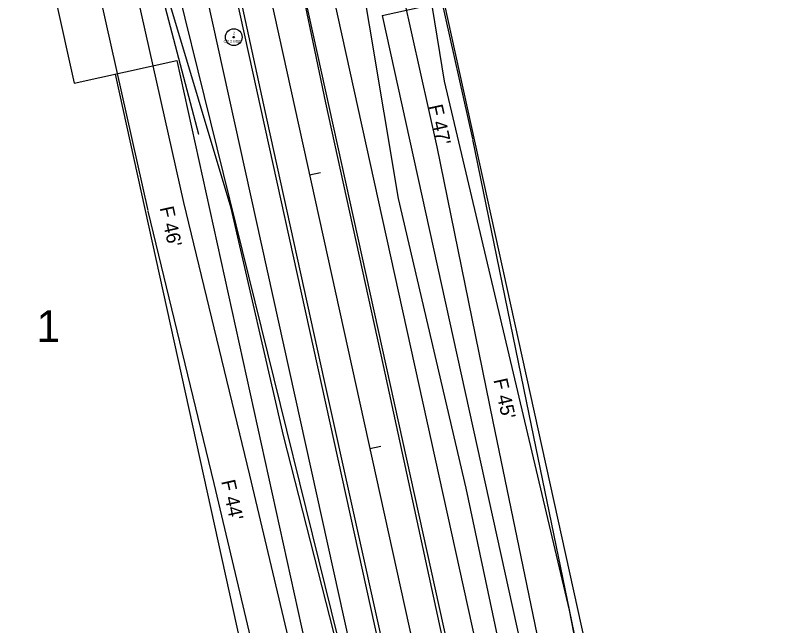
# Model space of a CAD drawing. Extents: x 2519952 to 2531965, y 848341 to 887632.
# Drawn here: x 2524424.7 to 2524699.1, y 869571 to 869788.7 of the extents above; entities that cross this region are included whole.
import ezdxf

# ---------------------------------------------------------------- set-up
doc = ezdxf.new("R2010")
doc.units = 0
for name, color, linetype in [('RD_EV_JW', 7, 'Continuous'), ('RD_EX_DV_Prop', 7, 'Continuous'), ('RD_EX_DV_TX_Prop', 7, 'Continuous'), ('RD_EX_H2O', 7, 'Continuous'), ('RD_EX_Road', 7, 'Continuous'), ('RD_EX_RW', 7, 'Continuous'), ('RD_EX_VEG', 7, 'Continuous'), ('RD_HC_Cl', 7, 'Continuous'), ('RD_HC_Data', 7, 'Continuous'), ('RD_HC_Data_Tic', 7, 'Continuous'), ('RD_HC_txCode', 7, 'Continuous'), ('RD_PD_CstnLmt', 7, 'Continuous'), ('RD_PD_DR_ErosCtrl', 7, 'Continuous'), ('RD_PD_Final_TrvlWay', 7, 'Continuous'), ('RD_PD_GR', 7, 'Continuous'), ('RD_PD_RW', 7, 'Continuous'), ('RD_PD_TX_CstnLmt', 7, 'Continuous'), ('RD_SMD_Locator', 7, 'Continuous')]:
    doc.layers.add(name, color=color, linetype=linetype)

msp = doc.modelspace()

# ---------------------------------------------------------------- linework, layer by layer
at = {"layer": 'RD_EV_JW'}
for points in [[(2524642.32, 869355.11), (2524607.87, 869514.61), (2524585.46, 869620.06), (2524561.39, 869723.4), (2524545.88, 869815.87), (2524534.52, 869900.16), (2524515.28, 869909.5)], [(2524525.2, 869274.67), (2524564.88, 869322.7), (2524583.4, 869339.87), (2524580.23, 869387.75), (2524545.19, 869541.45), (2524520.38, 869638.82), (2524501.71, 869719.92), (2524478.36, 869797.79), (2524468.19, 869836.51), (2524457.95, 869873.93)]]:
    msp.add_lwpolyline(points, dxfattribs=at)
at = {"layer": 'RD_EX_DV_Prop'}
for p, q in [((2524381.12, 870057.49), (2524445.63, 869764.51)), ((2524555.5, 869788.71), (2524663.02, 869300.4)), ((2524445.63, 869764.51), (2524482.25, 869772.58)), ((2524482.25, 869772.58), (2524589.78, 869284.28)), ((2524482.25, 869772.58), (2524589.78, 869284.28))]:
    msp.add_line(p, q, dxfattribs=at)
at = {"layer": 'RD_EX_H2O'}
msp.add_lwpolyline([(2524490.19, 869746.15), (2524461.13, 869856.58), (2524453.72, 869867.75), (2524467.93, 869899.58), (2524515.02, 869910.74), (2524525.28, 869911.03)], dxfattribs=at)
at = {"layer": 'RD_EX_Road'}
for p, q in [((2524535.42, 869757.49), (2524515.03, 869855.95)), ((2524514.45, 869751.33), (2524492.92, 869850.93)), ((2524556.02, 869663.74), (2524535.42, 869757.49)), ((2524534.79, 869658.81), (2524514.45, 869751.33)), ((2524576.96, 869567.21), (2524556.02, 869663.74)), ((2524556.56, 869561.19), (2524534.79, 869658.81))]:
    msp.add_line(p, q, dxfattribs=at)
at = {"layer": 'RD_EX_RW'}
for p, q in [((2524381.12, 870057.49), (2524445.63, 869764.51)), ((2524555.5, 869788.7), (2524592.12, 869796.77)), ((2524555.5, 869788.7), (2524663.02, 869300.4)), ((2524445.63, 869764.51), (2524482.25, 869772.57)), ((2524482.25, 869772.57), (2524589.78, 869284.28))]:
    msp.add_line(p, q, dxfattribs=at)
at = {"layer": 'RD_EX_VEG'}
for points in [[(2524497.69, 869223.25), (2524589.7, 869304), (2524542.03, 869557.84), (2524469.4, 869851.91), (2524466.51, 869881.65)], [(2524696.2, 869380.99), (2524663.62, 869364.09), (2524622.38, 869576.48), (2524577.79, 869765.19), (2524559.81, 869875.59)]]:
    msp.add_lwpolyline(points, dxfattribs=at)
at = {"layer": 'RD_HC_Cl'}
msp.add_line((2524338.62, 870599.23), (2524895.21, 868071.59), dxfattribs=at)
at = {"layer": 'RD_HC_Data'}
for radius in [3, 0.282]:
    msp.add_circle((2524502.59, 869780.94), radius, dxfattribs=at)
at = {"layer": 'RD_HC_Data_Tic'}
for p, q in [((2524529.63, 869731.81), (2524533.53, 869732.67)), ((2524551.13, 869634.15), (2524555.04, 869635.01))]:
    msp.add_line(p, q, dxfattribs=at)
at = {"layer": 'RD_PD_CstnLmt'}
for p, q in [((2524553.2, 869839.4), (2524575.06, 869741.81)), ((2524462.78, 869819.48), (2524484.63, 869721.9)), ((2524575.06, 869741.81), (2524595.06, 869643.82)), ((2524484.63, 869721.9), (2524508.16, 869624.69)), ((2524595.06, 869643.82), (2524615.32, 869545.89)), ((2524508.16, 869624.69), (2524531.24, 869527.37))]:
    msp.add_line(p, q, dxfattribs=at)
at = {"layer": 'RD_PD_DR_ErosCtrl'}
for p, q in [((2524565.89, 869842.24), (2524587.75, 869744.65)), ((2524450.09, 869816.64), (2524471.94, 869719.06)), ((2524587.8, 869744.41), (2524607.8, 869646.42)), ((2524471.99, 869718.84), (2524495.52, 869621.63)), ((2524607.79, 869646.45), (2524628.05, 869548.52)), ((2524495.51, 869621.68), (2524518.59, 869524.37))]:
    msp.add_line(p, q, dxfattribs=at)
at = {"layer": 'RD_PD_Final_TrvlWay'}
for p, q in [((2524439.2, 870198.28), (2524713.39, 868953.11)), ((2524415.76, 870193.11), (2524689.95, 868947.95))]:
    msp.add_line(p, q, dxfattribs=at)
at = {"layer": 'RD_PD_GR'}
for p, q in [((2524529.34, 869835.42), (2524687.94, 869115.18)), ((2524593.89, 869337.66), (2524486.37, 869825.96))]:
    msp.add_line(p, q, dxfattribs=at)
at = {"layer": 'RD_PD_RW'}
for p, q in [((2524577.47, 869793.54), (2524685, 869305.24)), ((2524460.28, 869767.74), (2524594.69, 869157.36))]:
    msp.add_line(p, q, dxfattribs=at)
at = {"layer": 'RD_SMD_Locator'}
for centre in [(2524502.59, 869780.94), (2524577.79, 869765.19), (2524535.42, 869757.49), (2524514.45, 869751.33), (2524490.19, 869746.15), (2524561.39, 869723.4), (2524501.71, 869719.92), (2524556.02, 869663.74), (2524534.79, 869658.81), (2524520.38, 869638.82), (2524585.46, 869620.06), (2524622.38, 869576.48)]:
    msp.add_circle(centre, 0.001, dxfattribs=at)

# ---------------------------------------------------------------- texts
at = {"layer": 'RD_EX_DV_TX_Prop'}
msp.add_text('1', height=11.32, dxfattribs=at).set_placement((2524432.23, 869672.11))
at = {"layer": 'RD_HC_txCode'}
for s, p in [('2', (2524502.31, 869781.94)), ('CP 2 MSC', (2524498.96, 869778.94))]:
    msp.add_text(s, height=1, dxfattribs=at).set_placement(p)
at = {"layer": 'RD_PD_CstnLmt'}
for s, p in [("F 46'", (2524476.14, 869720.03)), ("F 44'", (2524498.08, 869622.46))]:
    msp.add_text(s, height=5, rotation=282.4185, dxfattribs=at).set_placement(p)
at = {"layer": 'RD_PD_TX_CstnLmt'}
for s, p in [("F 47'", (2524572.11, 869756.37)), ("F 45'", (2524595.2, 869658.64))]:
    msp.add_text(s, height=5, rotation=282.4185, dxfattribs=at).set_placement(p)

doc.saveas('drawing.dxf')
